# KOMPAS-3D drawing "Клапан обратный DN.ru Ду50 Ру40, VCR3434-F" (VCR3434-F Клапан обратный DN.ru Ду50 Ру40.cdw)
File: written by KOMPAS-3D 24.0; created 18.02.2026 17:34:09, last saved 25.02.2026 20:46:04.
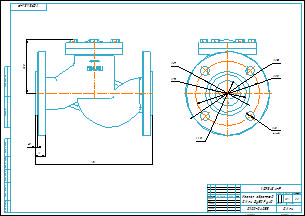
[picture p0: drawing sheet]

Document properties: art: D100-04055; Автор: R2D2; Форматы листов документа: A2; Полное имя файла: VCR3434-F Клапан обратный DN.ru Ду50 Ру40.m3d; Масса: 11.2; Наименование: Клапан обратный DN.ru Ду50 Ру40; Количество листов документа: 1; Примечание: D100-04055

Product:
- Part/product: Клапан обратный DN.ru Ду50 Ру40  | designation VCR3434-F
    Масса: 11.2
    Раздел спецификации: Прочие изделия
    Форматы листов документа: A2
    Примечание: D100-04055
    additional columns: D100-04055

Views: Вид 1, Спереди
Referenced files in E:\Работа\Зайцев\VCR3434-F Клапан обратный DN.ru Ду15-300\DN50\: VCR3434-F Клапан обратный DN.ru Ду50 Ру40.m3d
Referenced files in E:\Работа\Зайцев\Для компаса\: чертеж DN.ru А3.cdt
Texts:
  VCR3434-F
  чертеж DN.ru А3.cdt
  Клапан обратный
  DN.ru Ду50 Ру40
  prop
  Клапан обратный DN.ru Ду50 Ру40
  VCR3434-F Клапан обратный DN.ru Ду50 Ру40
Dimensions and other numbers on the sheet: 0; 3; 2; 4; 87; 73; 50; 18; 4 отв.; 165; 125; 1:1; 1; 11,2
